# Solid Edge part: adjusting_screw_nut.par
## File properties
Title: Adjusting screw nut
Author: Abhinav Rai
Template: Normal.par
Last saved by: Cadcim
Revision: 12
Application: Solid Edge
Material: aluminum
Accuracy: 0.99
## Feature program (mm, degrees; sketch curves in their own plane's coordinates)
sketch for "unnamed RevolvedProtrusion 1" plane through (0, 0, 0) normal (0, -1, 0) x-axis (1, 0, 0)
  line (38.1, 9.7462) -> (74.676, 9.7462)
  line (76.2, 8.2222) -> (74.676, 9.7462)
  line (76.2, -26.8298) -> (76.2, 8.2222)
  line (76.2, -26.8298) -> (74.676, -28.3538)
  line (74.676, -28.3538) -> (47.625, -28.3538)
  line (47.625, -28.3538) -> (47.625, -60.1038)
  line (47.625, -60.1038) -> (38.1, -60.1038)
  line (38.1, -60.1038) -> (38.1, 9.7462)
revolve "unnamed RevolvedProtrusion 1" add full turn 360 deg
sketch for "Hole_1" plane through (76.2, 0, 0) normal (1, 0, 0) x-axis (0, 1, 0)
  hole centre (0, -9.3038) bore radius 9.5123
hole "Hole_1" diameter 19.0246 finite  VBottomAngle = 118 deg
pattern "unnamed Pattern 1" of "Hole_1"
pattern "unnamed Pattern 2"
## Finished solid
Body 1: solid body, 16 faces, 16 edges, 4 vertices.
  Faces by surface: cylinder 7, cone 6, plane 3
  Edges by curve: circle 12, intersection 4
Bounding box of the edges (mm): 152.400 x 152.400 x 69.850, from (-76.2, -76.2, -60.1038) to (76.2, 76.2, 9.7462).
Cylindrical faces by radius (mm): R9.5123 x4, R38.1 x1, R47.625 x1, R76.2 x1
Conical faces (half-angle, radius in mm at the cone's reference point): 45 deg R74.676 x1, 45 deg R76.2 x1, 59 deg R9.5123 x4
Planar faces by outward normal: +z 1, -z 2
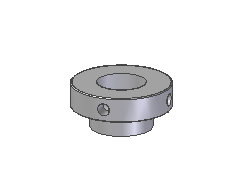
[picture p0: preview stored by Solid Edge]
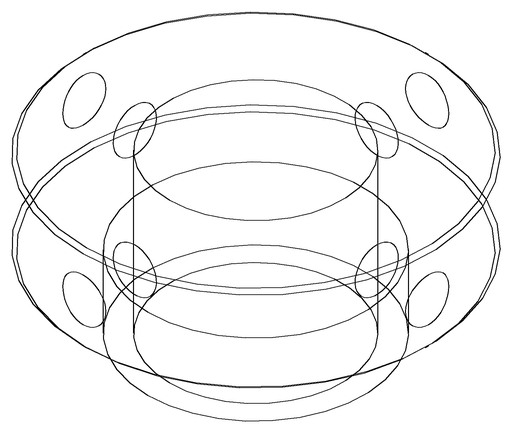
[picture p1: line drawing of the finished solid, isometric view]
